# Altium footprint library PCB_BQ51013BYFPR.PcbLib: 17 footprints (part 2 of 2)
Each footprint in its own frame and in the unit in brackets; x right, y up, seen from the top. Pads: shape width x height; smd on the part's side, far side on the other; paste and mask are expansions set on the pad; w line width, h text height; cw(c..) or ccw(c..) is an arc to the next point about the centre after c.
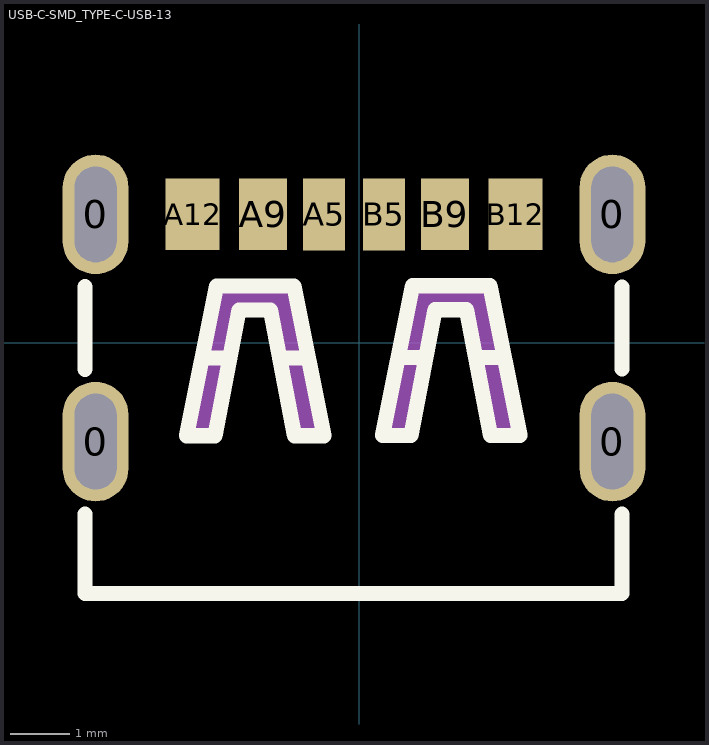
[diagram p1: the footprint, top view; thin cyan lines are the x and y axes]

## USB-C-SMD_TYPE-C-USB-13 [mm]
height 2.65
pads (10):
  oval 1.1x2 hole 0.7 slot 1.6 at 90 deg: 0(-4.407,-1.652) 0(-4.407,2.148) 0(4.233,-1.652) 0(4.233,2.148)
  rect 0.7x1.2 smd: A5(-0.587,2.146) B5(0.413,2.146)
  rect 0.8x1.2 smd: A9(-1.607,2.148) B9(1.433,2.15)
  rect 0.9x1.2 smd: A12(-2.787,2.148) B12(2.613,2.148)
Top Overlay:
  lines w0.254: -4.587,-2.862 -4.587,-4.191 4.393,-4.191 4.393,-2.867 ; -4.587,-0.442 -4.587,0.938 ; -2.586,-0.253 -2.188,-0.253 ; -1.287,-0.252 -0.887,-0.252 ; 0.69,-0.247 1.089,-0.247 ; 1.99,-0.247 2.39,-0.247 ; 4.393,-0.438 4.393,0.933 ; -2.886,-1.553 -2.411,-1.553 -2.01,0.548 -1.481,0.548 -1.083,-1.553 -0.587,-1.553 -1.088,0.949 -2.388,0.949 -2.886,-1.553 ; 0.391,-1.548 0.866,-1.548 1.267,0.553 1.795,0.553 2.194,-1.548 2.689,-1.548 2.189,0.954 0.889,0.954 0.391,-1.548
Top Paste:
  region: -4.957,2.598 -4.957,2.707 -4.873,2.909 -4.719,3.064 -4.516,3.148 -4.298,3.148 -4.095,3.064 -3.941,2.909 -3.857,2.707 -3.857,2.598 -3.857,1.698 -3.857,1.588 -3.941,1.386 -4.095,1.231 -4.298,1.148 -4.516,1.148 -4.719,1.231 -4.873,1.386 -4.957,1.588 -4.957,1.698
  region: 3.683,2.598 3.683,2.707 3.767,2.909 3.921,3.064 4.124,3.148 4.342,3.148 4.545,3.064 4.699,2.909 4.783,2.707 4.783,2.598 4.783,1.698 4.783,1.588 4.699,1.386 4.545,1.231 4.342,1.148 4.124,1.148 3.921,1.231 3.767,1.386 3.683,1.588 3.683,1.698
  region: 3.683,-1.202 3.683,-1.093 3.767,-0.891 3.921,-0.736 4.124,-0.652 4.342,-0.652 4.545,-0.736 4.699,-0.891 4.783,-1.093 4.783,-1.202 4.783,-2.102 4.783,-2.212 4.699,-2.414 4.545,-2.569 4.342,-2.652 4.124,-2.652 3.921,-2.569 3.767,-2.414 3.683,-2.212 3.683,-2.102
  region: -4.957,-1.202 -4.957,-1.093 -4.873,-0.891 -4.719,-0.736 -4.516,-0.652 -4.298,-0.652 -4.095,-0.736 -3.941,-0.891 -3.857,-1.093 -3.857,-1.202 -3.857,-2.102 -3.857,-2.212 -3.941,-2.414 -4.095,-2.569 -4.298,-2.652 -4.516,-2.652 -4.719,-2.569 -4.873,-2.414 -4.957,-2.212 -4.957,-2.102
  region: -3.237,2.748 -2.337,2.748 -2.337,1.548 -3.237,1.548
  region: -2.007,2.748 -1.207,2.748 -1.207,1.548 -2.007,1.548
  region: -0.937,2.746 -0.237,2.746 -0.237,1.546 -0.937,1.546
  region: 0.063,2.746 0.763,2.746 0.763,1.546 0.063,1.546
  region: 1.033,2.75 1.833,2.75 1.833,1.55 1.033,1.55
  region: 2.163,2.748 3.063,2.748 3.063,1.548 2.163,1.548
Mechanical 15:
  region: -2.427,-1.531 -1.967,0.509 -1.407,0.529 -1.027,-1.551 -0.467,-1.551 -1.067,0.989 -2.367,0.969 -2.867,-1.531
  region: 0.813,-1.531 1.273,0.509 1.833,0.529 2.213,-1.551 2.773,-1.551 2.173,0.989 0.873,0.969 0.373,-1.531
